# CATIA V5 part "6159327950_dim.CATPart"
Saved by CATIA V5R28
Part number: 6159327950_dim
Source: made
Property "PROI_CREATED_ON": "12/17/2008 9:21:37 AM"
Property "BLANK_DRAWING": "--"
Property "DRAWN_BY": "FPA"
Property "FINISH": "--"
Property "HEAT_TREATMENT": "ASSIGN"
Property "MATERIAL": "ASSIGN"
Property "PROJECT": "--"
Property "PROTOTYPE_NO": "--"
Property "RELATED_DRAWING": "--"
Property "COMPLETE_MATERIAL": "ASSIGN-ASSIGN"
Property "DESCRIPTION": "AXD + AXM-SX Core"
Property "DRAWING_EXIST": "--"
Property "MANUFACTURER": "--"
Property "MANUFACTURER_2": "--"
Property "MANUFACTURER_REF": "--"
Property "TYPE_PART": "--"
Property "TODAY_DATE": "2026/03/23"
Property "PDMREV": "01.0"
Property "PDMRL": "Production"
Property "PROI_REVISION": "01"
Property "PROI_VERSION": "0"
Property "PROI_RELEASE": "Production"
Property "PTC_MODIFIED": false
Property "MFG_WP_MATERIAL": "ASSIGN"
Property "COMPANY_CODE": "---"
Property "DESCRIPTION_JP": "--"
Property "PQP_DOCUMENT": "--"
Property "GHOST": false
Property "NO_PART": false
Property "REFERENCE": "6159327950_DIM"
Property "PTC_WM_ITERATION": "0"
Property "PTC_WM_VERSION": "01.0"
Property "PTC_WM_CREATED_ON": "24-Mar-26 09:23:24 AM"
Property "PTC_WM_MODIFIED_ON": "24-Mar-26 09:23:24 AM"
Property "PTC_WM_NAME": "6159327950_dim.prt"
Property "PTC_WM_NUMBER": "6159327950_DIM.PRT"
Property "PTC_WM_LIFECYCLE_STATE": "Production"
Property "PTC_WM_LIFECYCLE": "Design_Process"
Property "PTC_WM_REVISION": "01"
Property "PTC_WM_CREATED_BY": "Florian Pavageau (Grefpav) (Grefpav: CPD)"
Property "PTC_WM_MODIFIED_BY": "Florian Pavageau (Grefpav) (Grefpav: CPD)"
Property "PTC_ORGANIZATION_ID": "CPD"
Property "PTC_WM_LOCATION": "/Products/CONTROLLERS/A1770 - CX4 - SMART DRIVE - LEAN/9-01-Dimensional Drawings"
Property "PTC_WM_PART_NAME": "6159327950_dim.prt"
Property "PTC_WM_PART_NUMBER": "6159327950_DIM"
Property "PTC_WM_TEAM": "Default"
Property "PTC_COMMON_NAME": "6159327950_dim.prt"
Property "PTC_MASTER_MATERIAL": "ASSIGN"
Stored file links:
  d:\ptc\Echange\temp\6159327950_dim.CATPart

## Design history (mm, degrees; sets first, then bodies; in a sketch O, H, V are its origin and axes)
AxisSystem1 "CS0": origin (0, 0, 0), X (1, 0, 0), Y (0, 1, 0), Z (0, 0, 1)
Set1
  DatumSurface1 "Sheet.1"
  DatumSurface2 "Sheet.2"
  DatumSurface3 "Sheet.3"
  DatumSurface4 "Sheet.4"
  DatumSurface5 "Sheet.5"
  DatumSurface6 "Sheet.6"
  DatumSurface7 "Sheet.7"
  DatumSurface8 "Sheet.8"
  DatumSurface9 "Sheet.9"
  DatumSurface10 "Sheet.10"
  DatumSurface11 "Sheet.11"
  DatumSurface12 "Sheet.12"
  DatumSurface13 "Sheet.13"
  DatumSurface14 "Sheet.14"
  DatumSurface15 "Sheet.15"
  DatumSurface16 "Sheet.16"
  DatumSurface17 "Sheet.17"
  DatumSurface18 "Sheet.18"
  DatumSurface19 "Sheet.19"
  DatumSurface20 "Sheet.20"
  DatumSurface21 "Sheet.21"
  DatumSurface22 "Sheet.22"
  DatumSurface23 "Sheet.23"
  DatumSurface24 "Sheet.24"
  DatumSurface25 "Sheet.25"
  DatumSurface26 "Sheet.26"
  DatumSurface27 "Sheet.27"
  DatumSurface28 "Sheet.28"
  DatumSurface29 "Sheet.29"
  DatumSurface30 "Sheet.30"
  DatumSurface31 "Sheet.31"
  DatumSurface32 "Sheet.32"
  DatumSurface33 "Sheet.33"
  DatumSurface34 "Sheet.34"
  DatumSurface35 "Sheet.35"
  DatumSurface36 "Sheet.36"
  DatumSurface37 "Sheet.37"
  DatumSurface38 "Sheet.38"
  DatumSurface39 "Sheet.39"
  DatumSurface40 "Sheet.40"
  DatumSurface41 "Sheet.41"
  DatumSurface42 "Sheet.42"
  DatumSurface43 "Sheet.43"
  DatumSurface44 "Sheet.44"
  DatumSurface45 "Sheet.45"
  DatumSurface46 "Sheet.46"
  DatumSurface47 "Sheet.47"
  DatumSurface48 "Sheet.48"
  DatumSurface49 "Sheet.49"
  DatumSurface50 "Sheet.50"
  DatumSurface51 "Sheet.51"
  DatumSurface52 "Sheet.52"
  DatumSurface53 "Sheet.53"
  DatumSurface54 "Sheet.54"
  DatumSurface55 "Sheet.55"
  DatumSurface56 "Sheet.56"
  DatumSurface57 "Sheet.57"
  DatumSurface58 "Sheet.58"
  DatumSurface59 "Sheet.59"
  DatumSurface60 "Sheet.60"
  DatumSurface61 "Sheet.61"
  DatumSurface62 "Sheet.62"
  DatumSurface63 "Sheet.63"
  DatumSurface64 "Sheet.64"
  DatumSurface65 "Sheet.65"
  DatumSurface66 "Sheet.66"
  DatumSurface67 "Sheet.67"
  DatumSurface68 "Sheet.68"
  DatumSurface69 "Sheet.69"
  DatumSurface70 "Sheet.70"
  DatumSurface71 "Sheet.71"
  DatumSurface72 "Sheet.72"
  DatumSurface73 "Sheet.73"
  DatumSurface74 "Sheet.74"
  DatumSurface75 "Sheet.75"
  DatumSurface76 "Sheet.76"
  DatumSurface77 "Sheet.77"
  DatumSurface78 "Sheet.78"
  DatumSurface79 "Sheet.79"
  DatumSurface80 "Sheet.80"
  DatumSurface81 "Sheet.81"
  DatumSurface82 "Sheet.82"
  DatumSurface83 "Sheet.83"
  DatumSurface84 "Sheet.84"
  DatumSurface85 "Sheet.85"
  DatumSurface86 "Sheet.86"
  DatumSurface87 "Sheet.87"
  DatumSurface88 "Sheet.88"
  DatumSurface89 "Sheet.89"
  DatumSurface90 "Sheet.90"
  DatumSurface91 "Sheet.91"
  DatumSurface92 "Sheet.92"
  DatumSurface93 "Sheet.93"
  DatumSurface94 "Sheet.94"
  DatumSurface95 "Sheet.95"
  DatumSurface96 "Sheet.96"
  DatumSurface97 "Sheet.97"
  DatumSurface98 "Sheet.98"
  DatumSurface99 "Sheet.99"
  DatumSurface100 "Sheet.100"
  DatumSurface101 "Sheet.101"
  DatumSurface102 "Sheet.102"
  DatumSurface103 "Sheet.103"
  DatumSurface104 "Sheet.104"
  DatumSurface105 "Sheet.105"
  DatumSurface106 "Sheet.106"
  DatumSurface107 "Sheet.107"
  DatumSurface108 "Sheet.108"
  DatumSurface109 "Sheet.109"
  DatumSurface110 "Sheet.110"
  DatumSurface111 "Sheet.111"
  DatumSurface112 "Sheet.112"
  DatumSurface113 "Sheet.113"
  DatumSurface114 "Sheet.114"
  DatumSurface115 "Sheet.115"
  DatumSurface116 "Sheet.116"
  DatumSurface117 "Sheet.117"
  DatumSurface118 "Sheet.118"
  DatumSurface119 "Sheet.119"
  DatumSurface120 "Sheet.120"
  DatumSurface121 "Sheet.121"
  DatumSurface122 "Sheet.122"
  DatumSurface123 "Sheet.123"
  DatumSurface124 "Sheet.124"
  DatumSurface125 "Sheet.125"
  DatumSurface126 "Sheet.126"
  DatumSurface127 "Sheet.127"
  DatumSurface128 "Sheet.128"
  DatumSurface129 "Sheet.129"
  DatumSurface130 "Sheet.130"
  DatumSurface131 "Sheet.131"
  DatumSurface132 "Sheet.132"
  DatumSurface133 "Sheet.133"
  DatumSurface134 "Sheet.134"
  DatumSurface135 "Sheet.135"
  DatumSurface136 "Sheet.136"
  DatumSurface137 "Sheet.137"
  DatumSurface138 "Sheet.138"
  DatumSurface139 "Sheet.139"
  DatumSurface140 "Sheet.140"
  DatumSurface141 "Sheet.141"
  DatumSurface142 "Sheet.142"
  DatumSurface143 "Sheet.143"
  DatumSurface144 "Sheet.144"
  DatumSurface145 "Sheet.145"
  DatumSurface146 "Sheet.146"
  DatumSurface147 "Sheet.147"
  DatumSurface148 "Sheet.148"
  DatumSurface149 "Sheet.149"
  DatumSurface150 "Sheet.150"
  DatumSurface151 "Sheet.151"
  DatumSurface152 "Sheet.152"
  DatumSurface153 "Sheet.153"
  DatumSurface154 "Sheet.154"
  DatumSurface155 "Sheet.155"
  DatumSurface156 "Sheet.156"
  DatumSurface157 "Sheet.157"
  DatumSurface158 "Sheet.158"
  DatumSurface159 "Sheet.159"
  DatumSurface160 "Sheet.160"
  DatumSurface161 "Sheet.161"
  DatumSurface162 "Sheet.162"
  DatumSurface163 "Sheet.163"
  DatumSurface164 "Sheet.164"
  DatumSurface165 "Sheet.165"
  DatumSurface166 "Sheet.166"
  DatumSurface167 "Sheet.167"
  DatumSurface168 "Sheet.168"
  DatumSurface169 "Sheet.169"
  DatumSurface170 "Sheet.170"
  DatumSurface171 "Sheet.171"
  DatumSurface172 "Sheet.172"
  DatumSurface173 "Sheet.173"
  DatumSurface174 "Sheet.174"
  DatumSurface175 "Sheet.175"
  DatumSurface176 "Sheet.176"
  DatumSurface177 "Sheet.177"
  DatumSurface178 "Sheet.178"
  DatumSurface179 "Sheet.179"
  DatumSurface180 "Sheet.180"
  DatumSurface181 "Sheet.181"
  DatumSurface182 "Sheet.182"
  DatumSurface183 "Sheet.183"
  DatumSurface184 "Sheet.184"
  DatumSurface185 "Sheet.185"
  DatumSurface186 "Sheet.186"
  DatumSurface187 "Sheet.187"
  DatumSurface188 "Sheet.188"
  DatumSurface189 "Sheet.189"
  DatumSurface190 "Sheet.190"
  DatumSurface191 "Sheet.191"
  DatumSurface192 "Sheet.192"
  DatumSurface193 "Sheet.193"
  DatumSurface194 "Sheet.194"
  DatumSurface195 "Sheet.195"
  DatumSurface196 "Sheet.196"
  DatumSurface197 "Sheet.197"
  DatumSurface198 "Sheet.198"
  DatumSurface199 "Sheet.199"
  DatumSurface200 "Sheet.200"
  DatumSurface201 "Sheet.201"
  DatumSurface202 "Sheet.202"
  DatumSurface203 "Sheet.203"
  DatumSurface204 "Sheet.204"
  DatumSurface205 "Sheet.205"
  DatumSurface206 "Sheet.206"
  DatumSurface207 "Sheet.207"
  DatumSurface208 "Sheet.208"
  DatumSurface209 "Sheet.209"
  DatumSurface210 "Sheet.210"
  DatumSurface211 "Sheet.211"
  DatumSurface212 "Sheet.212"
  DatumSurface213 "Sheet.213"
  DatumSurface214 "Sheet.214"
  DatumSurface215 "Sheet.215"
  DatumSurface216 "Sheet.216"
  DatumSurface217 "Sheet.217"
  DatumSurface218 "Sheet.218"
  DatumSurface219 "Sheet.219"
  DatumSurface220 "Sheet.220"
  DatumSurface221 "Sheet.221"
  DatumSurface222 "Sheet.222"
  DatumSurface223 "Sheet.223"
  DatumSurface224 "Sheet.224"
  DatumSurface225 "Sheet.225"
  DatumSurface226 "Sheet.226"
  DatumSurface227 "Sheet.227"
  DatumSurface228 "Sheet.228"
  DatumSurface229 "Sheet.229"
  DatumSurface230 "Sheet.230"
  DatumSurface231 "Sheet.231"
  DatumSurface232 "Sheet.232"
  DatumSurface233 "Sheet.233"
  DatumSurface234 "Sheet.234"
  DatumSurface235 "Sheet.235"
  DatumSurface236 "Sheet.236"
  DatumSurface237 "Sheet.237"
  DatumSurface238 "Sheet.238"
  DatumSurface239 "Sheet.239"
  DatumSurface240 "Sheet.240"
  DatumSurface241 "Sheet.241"
  DatumSurface242 "Sheet.242"
  DatumSurface243 "Sheet.243"
  DatumSurface244 "Sheet.244"
  DatumSurface245 "Sheet.245"
  DatumSurface246 "Sheet.246"
  DatumSurface247 "Sheet.247"
  DatumSurface248 "Sheet.248"
  DatumSurface249 "Sheet.249"
  DatumSurface250 "Sheet.250"
  DatumSurface251 "Sheet.251"
  DatumSurface252 "Sheet.252"
  DatumSurface253 "Sheet.253"
  DatumSurface254 "Sheet.254"
  DatumSurface255 "Sheet.255"
  DatumSurface256 "Sheet.256"
  DatumSurface257 "Sheet.257"
  DatumSurface258 "Sheet.258"
  DatumSurface259 "Sheet.259"
  DatumSurface260 "Sheet.260"
  DatumSurface261 "Sheet.261"
  DatumSurface262 "Sheet.262"
  DatumSurface263 "Sheet.263"
  DatumSurface264 "Sheet.264"
  DatumSurface265 "Sheet.265"
  DatumSurface266 "Sheet.266"
  DatumSurface267 "Sheet.267"
  DatumSurface268 "Sheet.268"
  DatumSurface269 "Sheet.269"
  DatumSurface270 "Sheet.270"
  DatumSurface271 "Sheet.271"
  DatumSurface272 "Sheet.272"
  DatumSurface273 "Sheet.273"
  DatumSurface274 "Sheet.274"
  DatumSurface275 "Sheet.275"
  DatumSurface276 "Sheet.276"
  DatumSurface277 "Sheet.277"
  DatumSurface278 "Sheet.278"
  DatumSurface279 "Sheet.279"
  DatumSurface280 "Sheet.280"
  DatumSurface281 "Sheet.281"
  DatumSurface282 "Sheet.282"
  DatumSurface283 "Sheet.283"
  DatumSurface284 "Sheet.284"
  DatumSurface285 "Sheet.285"
  DatumSurface286 "Sheet.286"
  DatumSurface287 "Sheet.287"
  DatumSurface288 "Sheet.288"
  DatumSurface289 "Sheet.289"
  DatumSurface290 "Sheet.290"
  DatumSurface291 "Sheet.291"
  DatumSurface292 "Sheet.292"
  DatumSurface293 "Sheet.293"
  DatumSurface294 "Sheet.294"
  DatumSurface295 "Sheet.295"
  DatumSurface296 "Sheet.296"
  DatumSurface297 "Sheet.297"
  DatumSurface298 "Sheet.298"
  DatumSurface299 "Sheet.299"
  DatumSurface300 "Sheet.300"
  DatumSurface301 "Sheet.301"
  DatumSurface302 "Sheet.302"
  Plane1 "RIGHT": stored without definition
  Plane2 "TOP": stored without definition
  Plane3 "FRONT": stored without definition
  Line1 "A_1": stored without definition
  Line2 "A_2": stored without definition
  Line3 "A_3": stored without definition
  Line4 "A_4": stored without definition
Body1 "PartBody" (main body)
